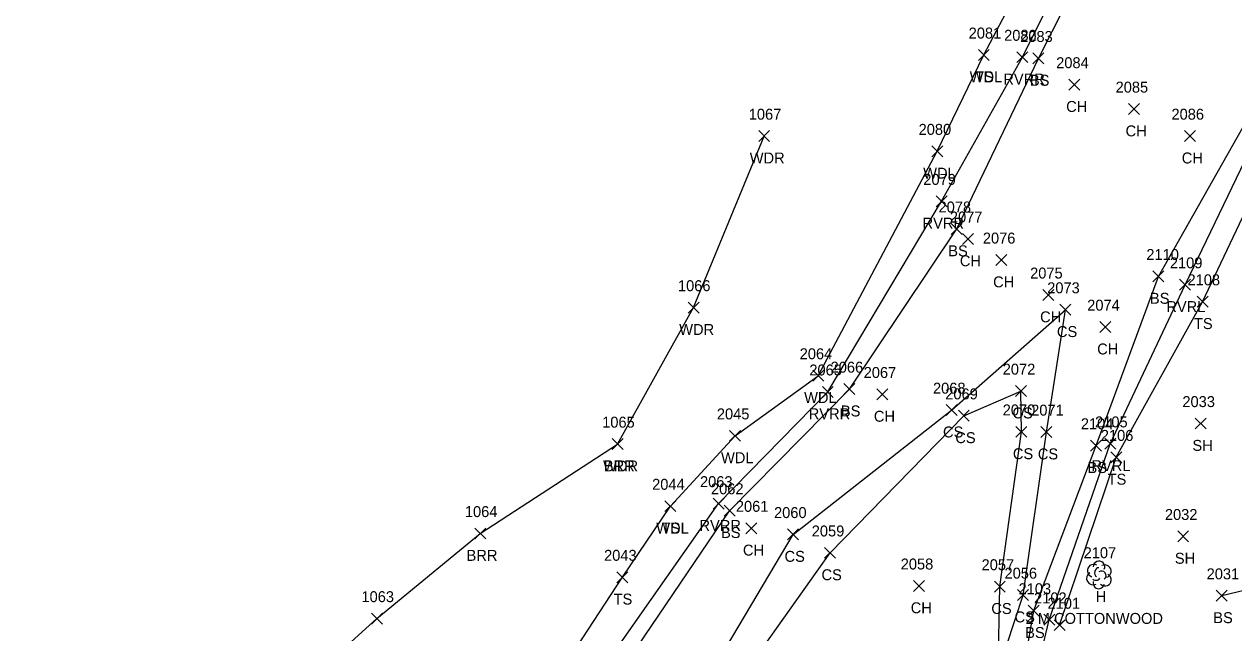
# Model space of a CAD drawing. Extents: x 1600395 to 1603269, y 874955 to 877143.
# Drawn here: x 1601689.2 to 1601910.3, y 875295.5 to 875406.7 of the extents above; entities that cross this region are included whole.
import ezdxf

# ---------------------------------------------------------------- set-up
doc = ezdxf.new("R2010")
doc.units = 0
for name, color, linetype in [('L_A', 7, 'Continuous'), ('L_C', 7, 'Continuous'), ('L_I', 7, 'Continuous'), ('L_TIC', 7, 'Continuous'), ('LABL', 7, 'Continuous'), ('LAWA', 7, 'Continuous'), ('LAWE', 7, 'Continuous'), ('LELB', 7, 'Continuous'), ('LTD', 7, 'Continuous')]:
    doc.layers.add(name, color=color, linetype=linetype)

msp = doc.modelspace()

# ---------------------------------------------------------------- linework, layer by layer
at = {"layer": 'L_TIC'}
for points in [[(1601863.61, 875400.11), (1601865.61, 875402.11)], [(1601865.61, 875400.11), (1601863.61, 875402.11)], [(1601863.61, 875400.11), (1601865.61, 875402.11)], [(1601865.61, 875400.11), (1601863.61, 875402.11)], [(1601870.66, 875399.7), (1601872.66, 875401.7)], [(1601872.66, 875399.7), (1601870.66, 875401.7)], [(1601873.59, 875399.48), (1601875.59, 875401.48)], [(1601875.59, 875399.48), (1601873.59, 875401.48)], [(1601880.17, 875394.69), (1601882.17, 875396.69)], [(1601882.17, 875394.69), (1601880.17, 875396.69)], [(1601891.03, 875390.23), (1601893.03, 875392.23)], [(1601893.03, 875390.23), (1601891.03, 875392.23)], [(1601823.47, 875385.28), (1601825.47, 875387.28)], [(1601825.47, 875385.28), (1601823.47, 875387.28)], [(1601901.3, 875385.28), (1601903.3, 875387.28)], [(1601903.3, 875385.28), (1601901.3, 875387.28)], [(1601855.11, 875382.51), (1601857.11, 875384.51)], [(1601857.11, 875382.51), (1601855.11, 875384.51)], [(1601855.9, 875373.37), (1601857.9, 875375.37)], [(1601857.9, 875373.37), (1601855.9, 875375.37)], [(1601858.67, 875368.32), (1601860.67, 875370.32)], [(1601860.67, 875368.32), (1601858.67, 875370.32)], [(1601860.74, 875366.49), (1601862.74, 875368.49)], [(1601862.74, 875366.49), (1601860.74, 875368.49)], [(1601866.82, 875362.64), (1601868.82, 875364.64)], [(1601868.82, 875362.64), (1601866.82, 875364.64)], [(1601895.52, 875359.64), (1601897.52, 875361.64)], [(1601897.52, 875359.64), (1601895.52, 875361.64)], [(1601900.39, 875358.12), (1601902.39, 875360.12)], [(1601902.39, 875358.12), (1601900.39, 875360.12)], [(1601875.4, 875356.25), (1601877.4, 875358.25)], [(1601877.4, 875356.25), (1601875.4, 875358.25)], [(1601903.6, 875355.02), (1601905.6, 875357.02)], [(1601905.6, 875355.02), (1601903.6, 875357.02)], [(1601810.58, 875353.94), (1601812.58, 875355.94)], [(1601812.58, 875353.94), (1601810.58, 875355.94)], [(1601878.53, 875353.56), (1601880.53, 875355.56)], [(1601880.53, 875353.56), (1601878.53, 875355.56)], [(1601878.53, 875353.56), (1601880.53, 875355.56)], [(1601880.53, 875353.56), (1601878.53, 875355.56)], [(1601885.84, 875350.38), (1601887.84, 875352.38)], [(1601887.84, 875350.38), (1601885.84, 875352.38)], [(1601833.35, 875341.5), (1601835.35, 875343.5)], [(1601835.35, 875341.5), (1601833.35, 875343.5)], [(1601839.05, 875339.05), (1601841.05, 875341.05)], [(1601841.05, 875339.05), (1601839.05, 875341.05)], [(1601870.4, 875338.69), (1601872.4, 875340.69)], [(1601872.4, 875338.69), (1601870.4, 875340.69)], [(1601870.4, 875338.69), (1601872.4, 875340.69)], [(1601872.4, 875338.69), (1601870.4, 875340.69)], [(1601835.1, 875338.54), (1601837.1, 875340.54)], [(1601837.1, 875338.54), (1601835.1, 875340.54)], [(1601845.04, 875338.08), (1601847.04, 875340.08)], [(1601847.04, 875338.08), (1601845.04, 875340.08)], [(1601857.71, 875335.21), (1601859.71, 875337.21)], [(1601859.71, 875335.21), (1601857.71, 875337.21)], [(1601859.96, 875334.17), (1601861.96, 875336.17)], [(1601861.96, 875334.17), (1601859.96, 875336.17)], [(1601903.24, 875332.76), (1601905.24, 875334.76)], [(1601905.24, 875332.76), (1601903.24, 875334.76)], [(1601818.16, 875330.51), (1601820.16, 875332.51)], [(1601820.16, 875330.51), (1601818.16, 875332.51)], [(1601870.48, 875331.24), (1601872.48, 875333.24)], [(1601872.48, 875331.24), (1601870.48, 875333.24)], [(1601875.04, 875331.2), (1601877.04, 875333.2)], [(1601877.04, 875331.2), (1601875.04, 875333.2)], [(1601796.68, 875329), (1601798.68, 875331)], [(1601798.68, 875329), (1601796.68, 875331)], [(1601796.68, 875329), (1601798.68, 875331)], [(1601798.68, 875329), (1601796.68, 875331)], [(1601884.11, 875328.71), (1601886.11, 875330.71)], [(1601886.11, 875328.71), (1601884.11, 875330.71)], [(1601886.71, 875329.05), (1601888.71, 875331.05)], [(1601888.71, 875329.05), (1601886.71, 875331.05)], [(1601887.82, 875326.58), (1601889.82, 875328.58)], [(1601889.82, 875326.58), (1601887.82, 875328.58)], [(1601806.32, 875317.65), (1601808.32, 875319.65)], [(1601808.32, 875317.65), (1601806.32, 875319.65)], [(1601806.32, 875317.65), (1601808.32, 875319.65)], [(1601808.32, 875317.65), (1601806.32, 875319.65)], [(1601815.13, 875318.13), (1601817.13, 875320.13)], [(1601817.13, 875318.13), (1601815.13, 875320.13)], [(1601817.14, 875316.83), (1601819.14, 875318.83)], [(1601819.14, 875316.83), (1601817.14, 875318.83)], [(1601771.59, 875312.66), (1601773.59, 875314.66)], [(1601773.59, 875312.66), (1601771.59, 875314.66)], [(1601821.1, 875313.62), (1601823.1, 875315.62)], [(1601823.1, 875313.62), (1601821.1, 875315.62)], [(1601828.75, 875312.48), (1601830.75, 875314.48)], [(1601830.75, 875312.48), (1601828.75, 875314.48)], [(1601900.04, 875312.13), (1601902.04, 875314.13)], [(1601902.04, 875312.13), (1601900.04, 875314.13)], [(1601835.51, 875309.12), (1601837.51, 875311.12)], [(1601837.51, 875309.12), (1601835.51, 875311.12)], [(1601797.55, 875304.67), (1601799.55, 875306.67)], [(1601799.55, 875304.67), (1601797.55, 875306.67)], [(1601851.76, 875303.08), (1601853.76, 875305.08)], [(1601853.76, 875303.08), (1601851.76, 875305.08)], [(1601866.54, 875302.95), (1601868.54, 875304.95)], [(1601868.54, 875302.95), (1601866.54, 875304.95)], [(1601870.79, 875301.41), (1601872.79, 875303.41)], [(1601872.79, 875301.41), (1601870.79, 875303.41)], [(1601907.1, 875301.28), (1601909.1, 875303.28)], [(1601909.1, 875301.28), (1601907.1, 875303.28)], [(1601752.69, 875297.11), (1601754.69, 875299.11)], [(1601754.69, 875297.11), (1601752.69, 875299.11)], [(1601872.73, 875298.56), (1601874.73, 875300.56)], [(1601874.73, 875298.56), (1601872.73, 875300.56)], [(1601875.57, 875296.89), (1601877.57, 875298.89)], [(1601877.57, 875296.89), (1601875.57, 875298.89)], [(1601877.45, 875295.91), (1601879.45, 875297.91)], [(1601879.45, 875295.91), (1601877.45, 875297.91)]]:
    msp.add_lwpolyline(points, dxfattribs=at)
at = {"layer": 'LABL'}
msp.add_lwpolyline([(1601761.25, 875256.6), (1601746.27, 875257.43), (1601736.57, 875261.58), (1601732.87, 875273.21), (1601738.08, 875283.93), (1601753.69, 875298.11), (1601772.59, 875313.66), (1601797.68, 875330)], dxfattribs=at)
at = {"layer": 'LAWA'}
for points in [[(1601807.32, 875318.65), (1601819.16, 875331.51), (1601834.35, 875342.5), (1601856.11, 875383.51), (1601864.61, 875401.11)], [(1601797.68, 875330), (1601811.58, 875354.94), (1601824.47, 875386.28)]]:
    msp.add_lwpolyline(points, dxfattribs=at)
at = {"layer": 'LAWE'}
for points in [[(1601691.61, 874961.83), (1601690.19, 874993.06), (1601689.23, 875017.02), (1601693.18, 875046.24), (1601698.32, 875069.37), (1601704.73, 875096.64), (1601712.32, 875125.39), (1601726.38, 875151.58), (1601742.36, 875184.33), (1601749.84, 875201.82), (1601757.17, 875214.81), (1601763.47, 875228.29), (1601769.62, 875241.93), (1601778.23, 875255.27), (1601780.68, 875261.68), (1601794.38, 875288.12), (1601816.13, 875319.13), (1601836.1, 875339.54), (1601856.9, 875374.37), (1601871.66, 875400.7), (1601886.6, 875430.71)], [(1601739.84, 875093.18), (1601757.34, 875121.49), (1601768.46, 875137.84), (1601782.2, 875157.26), (1601805.12, 875181.22), (1601811.36, 875189.98), (1601818.62, 875191.89), (1601823.21, 875192.81), (1601844.15, 875211.08), (1601861.59, 875229.67), (1601864.03, 875235.31), (1601870.34, 875255.07), (1601872.91, 875271.96), (1601871.03, 875274.54), (1601876.57, 875297.89), (1601887.71, 875330.05), (1601901.39, 875359.12), (1601917.88, 875393.3), (1601921.98, 875399.3), (1601926.73, 875398.96), (1601927.66, 875400.9), (1601926.51, 875404.41), (1601936.61, 875427.42)]]:
    msp.add_lwpolyline(points, dxfattribs=at)
at = {"layer": 'LELB'}
for points in [[(1601782.88, 875259.7), (1601797.54, 875287.39), (1601818.14, 875317.83), (1601840.05, 875340.05), (1601859.67, 875369.32), (1601874.59, 875400.48), (1601889.55, 875430.01), (1601905.96, 875461.66), (1601915.86, 875481.25), (1601936.76, 875517.32), (1601948.53, 875545.36), (1601941.42, 875586.61)], [(1601870.72, 875282.07), (1601873.73, 875299.56), (1601885.11, 875329.71), (1601896.52, 875360.64), (1601915.58, 875394.32), (1601921.27, 875400.59), (1601925.94, 875399.76), (1601925.98, 875401.46), (1601925.1, 875405.41), (1601934.86, 875429.08), (1601950.13, 875458.97), (1601969.1, 875502.62), (1601979.94, 875529.95), (1601991.87, 875574.72)], [(1601864.61, 875401.11), (1601880.82, 875431.87), (1601901.14, 875463), (1601913.14, 875482.84), (1601933.08, 875520.64), (1601941.51, 875545.31)], [(1601878.45, 875296.91), (1601888.82, 875327.58), (1601904.6, 875356.02), (1601921.47, 875391.54), (1601923.26, 875397.15)], [(1601796.01, 875263.88), (1601812.14, 875283.83), (1601829.75, 875313.48), (1601858.71, 875336.21), (1601879.53, 875354.56)], [(1601867.26, 875288.48), (1601871.79, 875302.41), (1601876.04, 875332.2), (1601879.53, 875354.56)], [(1601799.58, 875261.84), (1601817.2, 875282.89), (1601836.51, 875310.12), (1601860.96, 875335.17), (1601871.4, 875339.69)], [(1601867.26, 875288.48), (1601867.54, 875303.95), (1601871.48, 875332.24), (1601871.4, 875339.69)], [(1601764.36, 875260.52), (1601777.02, 875268.04), (1601788.08, 875289.65), (1601798.55, 875305.67), (1601807.32, 875318.65)], [(1601884.02, 875279.82), (1601895.26, 875286.95), (1601914.13, 875289.88), (1601928.42, 875301.6), (1601942.41, 875315.55), (1601923.09, 875305.88), (1601908.1, 875302.28)]]:
    msp.add_lwpolyline(points, dxfattribs=at)
at = {"layer": 'LTD'}
msp.add_line((1601885.62, 875306.14), (1601885.62, 875306.14), dxfattribs=at)
msp.add_line((1601885.62, 875306.14), (1601885.62, 875306.14), dxfattribs=at)
msp.add_arc((1601885.67, 875307.58), 1.05, 335.5272, 180.9563, dxfattribs=at)
for centre, major_axis, ratio, start_param, end_param in [((1601884.83, 875306.81), (1.21, -0.51), 0.895232, 1.570796, 4.712389), ((1601886.66, 875306.73), (-1.14, -0.48), 0.949671, 1.570796, 4.712389), ((1601884.54, 875305.44), (0.58, -1.04), 0.959034, 3.141593, 6.283185), ((1601885.16, 875305.39), (-0.625, -0.083), 0.423636, 0, 3.141593), ((1601885.41, 875306.6), (-0.208, -0.792), 0.645439, 3.141593, 6.283185), ((1601886.12, 875305.98), (-0.5, 0.667), 0.989748, 3.141593, 6.283185), ((1601886.62, 875305.31), (-1.09, 0.79), 0.841452, 1.570796, 4.712389), ((1601885.62, 875304.64), (0.26, 1.06), 0.942809, 1.570796, 4.712389)]:
    msp.add_ellipse(centre, major_axis=major_axis, ratio=ratio, start_param=start_param, end_param=end_param, dxfattribs=at)

# ---------------------------------------------------------------- texts
at = {"layer": 'L_A'}
for s, p in [('WDL', (1601862.03, 875396.11)), ('TS', (1601863.02, 875396.11)), ('RVRR', (1601868.17, 875395.7)), ('BS', (1601873.03, 875395.48)), ('CH', (1601879.66, 875390.69)), ('CH', (1601890.52, 875386.23)), ('WDR', (1601821.83, 875381.28)), ('CH', (1601900.78, 875381.28)), ('WDL', (1601853.53, 875378.51)), ('RVRR', (1601853.41, 875369.37)), ('BS', (1601858.11, 875364.32)), ('CH', (1601860.23, 875362.49)), ('CH', (1601866.31, 875358.64)), ('BS', (1601894.96, 875355.64)), ('RVRL', (1601897.96, 875354.12)), ('CH', (1601874.89, 875352.25)), ('WDR', (1601808.94, 875349.94)), ('TS', (1601903.01, 875351.02)), ('CS', (1601877.97, 875349.56)), ('CS', (1601877.97, 875349.56)), ('CH', (1601885.33, 875346.38)), ('WDL', (1601831.77, 875337.5)), ('RVRR', (1601832.61, 875334.54)), ('BS', (1601838.49, 875335.05)), ('CS', (1601869.84, 875334.69)), ('CS', (1601869.84, 875334.69)), ('CH', (1601844.52, 875334.08)), ('CS', (1601857.15, 875331.21)), ('CS', (1601859.4, 875330.17)), ('SH', (1601902.73, 875328.76)), ('WDL', (1601816.58, 875326.51)), ('CS', (1601869.92, 875327.24)), ('CS', (1601874.48, 875327.2)), ('WDR', (1601795.04, 875325)), ('BRR', (1601795.17, 875325)), ('BS', (1601883.55, 875324.71)), ('RVRL', (1601884.28, 875325.05)), ('TS', (1601887.23, 875322.58)), ('WDL', (1601804.74, 875313.65)), ('TS', (1601805.73, 875313.65)), ('RVRR', (1601812.64, 875314.13)), ('BS', (1601816.58, 875312.83)), ('BRR', (1601770.08, 875308.66)), ('CH', (1601820.59, 875309.62)), ('CS', (1601828.19, 875308.48)), ('SH', (1601899.52, 875308.13)), ('CS', (1601834.95, 875305.12)), ('H', (1601885.05, 875301.14)), ('TS', (1601796.95, 875300.67)), ('CH', (1601851.25, 875299.08)), ('CS', (1601865.98, 875298.95)), ('CS', (1601870.23, 875297.41)), ('BS', (1601906.54, 875297.28)), ('BS', (1601872.17, 875294.56))]:
    msp.add_text(s, height=2, dxfattribs=at).set_placement(p)
at = {"layer": 'L_C'}
msp.add_text('2 M COTTONWOOD', height=2, dxfattribs=at).set_placement((1601872.24, 875297.14))
at = {"layer": 'L_I'}
for s, p in [('2081', (1601861.84, 875404.11)), ('2081', (1601861.84, 875404.11)), ('2082', (1601868.32, 875403.7)), ('2083', (1601871.25, 875403.48)), ('2084', (1601877.83, 875398.69)), ('2085', (1601888.69, 875394.23)), ('1067', (1601821.65, 875389.28)), ('2086', (1601898.9, 875389.28)), ('2080', (1601852.69, 875386.51)), ('2079', (1601853.55, 875377.37)), ('2078', (1601856.33, 875372.32)), ('2077', (1601858.41, 875370.49)), ('2076', (1601864.43, 875366.64)), ('2110', (1601894.31, 875363.64)), ('2109', (1601898.61, 875362.12)), ('2075', (1601873.07, 875360.25)), ('2108', (1601901.83, 875359.02)), ('1066', (1601808.71, 875357.94)), ('2073', (1601876.19, 875357.56)), ('2073', (1601876.19, 875357.56)), ('2074', (1601883.5, 875354.38)), ('2064', (1601830.96, 875345.5)), ('2066', (1601836.61, 875343.05)), ('2065', (1601832.72, 875342.54)), ('2067', (1601842.65, 875342.08)), ('2072', (1601868.06, 875342.69)), ('2072', (1601868.06, 875342.69)), ('2068', (1601855.32, 875339.21)), ('2069', (1601857.56, 875338.17)), ('2033', (1601900.9, 875336.76)), ('2045', (1601815.82, 875334.51)), ('2070', (1601868.06, 875335.24)), ('2071', (1601873.26, 875335.2)), ('1065', (1601794.86, 875333)), ('1065', (1601794.86, 875333)), ('2104', (1601882.34, 875332.71)), ('2105', (1601884.94, 875333.05)), ('2106', (1601885.99, 875330.58)), ('2044', (1601803.99, 875321.65)), ('2044', (1601803.99, 875321.65)), ('2063', (1601812.74, 875322.13)), ('2062', (1601814.75, 875320.83)), ('1064', (1601769.77, 875316.66)), ('2061', (1601819.29, 875317.62)), ('2060', (1601826.27, 875316.48)), ('2032', (1601897.7, 875316.13)), ('2059', (1601833.16, 875313.12)), ('2043', (1601795.21, 875308.67)), ('2107', (1601882.85, 875309.14)), ('2058', (1601849.42, 875307.08)), ('2057', (1601864.2, 875306.95)), ('2056', (1601868.39, 875305.41)), ('2031', (1601905.33, 875305.28)), ('1063', (1601750.87, 875301.11)), ('2103', (1601870.96, 875302.56)), ('2102', (1601873.79, 875300.89)), ('2101', (1601876.25, 875299.91))]:
    msp.add_text(s, height=2, dxfattribs=at).set_placement(p)

doc.saveas('drawing.dxf')
